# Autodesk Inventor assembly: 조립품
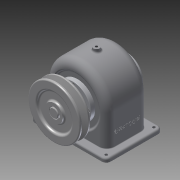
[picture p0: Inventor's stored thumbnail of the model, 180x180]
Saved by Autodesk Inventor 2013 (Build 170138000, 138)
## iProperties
Created: 2016-01
Part Number: 조립품
Document SubType Name: Assembly
Designer: cad10
Author: cad10
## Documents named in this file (16)
- C:\Documents and Settings\cad10\바탕 화면\460106V1031\조립품.iam
- C:\Documents and Settings\cad10\바탕 화면\460106V1031\키 - 6 x 6 x 22.ipt
- C:\Documents and Settings\cad10\바탕 화면\460106V1031\키 - 5 x 5 x 18.ipt
- C:\Documents and Settings\cad10\바탕 화면\460106V1031\뒤커버.ipt
- C:\Documents and Settings\cad10\바탕 화면\460106V1031\멈춤나사 - M4x10.ipt
- C:\Documents and Settings\cad10\바탕 화면\460106V1031\볼트 M3 x 8.ipt
- C:\Documents and Settings\cad10\바탕 화면\460106V1031\볼트 M3 x 10.ipt
- C:\Documents and Settings\cad10\바탕 화면\460106V1031\부시1.ipt
- C:\Documents and Settings\cad10\바탕 화면\460106V1031\부시2.ipt
- C:\Documents and Settings\cad10\바탕 화면\460106V1031\오일씰 28 40 8.ipt
- C:\Documents and Settings\cad10\바탕 화면\460106V1031\베어링 6203.ipt
- C:\Documents and Settings\cad10\바탕 화면\460106V1031\스퍼기어.ipt
- C:\Documents and Settings\cad10\바탕 화면\460106V1031\앞커버.ipt
- C:\Documents and Settings\cad10\바탕 화면\460106V1031\축.ipt
- C:\Documents and Settings\cad10\바탕 화면\460106V1031\V-벨트풀리.ipt
- C:\Documents and Settings\cad10\바탕 화면\460106V1031\본체.ipt
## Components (9 placed, 3 different names)
1. V-벨트풀리:1
2. ISO 4762 M3 x 10:1
3. ISO 4762 M3 x 10:2
4. ISO 4762 M3 x 10:3
5. ISO 4762 M3 x 10:4
6. ISO 4762 M3 x 8:1
7. ISO 4762 M3 x 8:2
8. ISO 4762 M3 x 8:3
9. ISO 4762 M3 x 8:4
